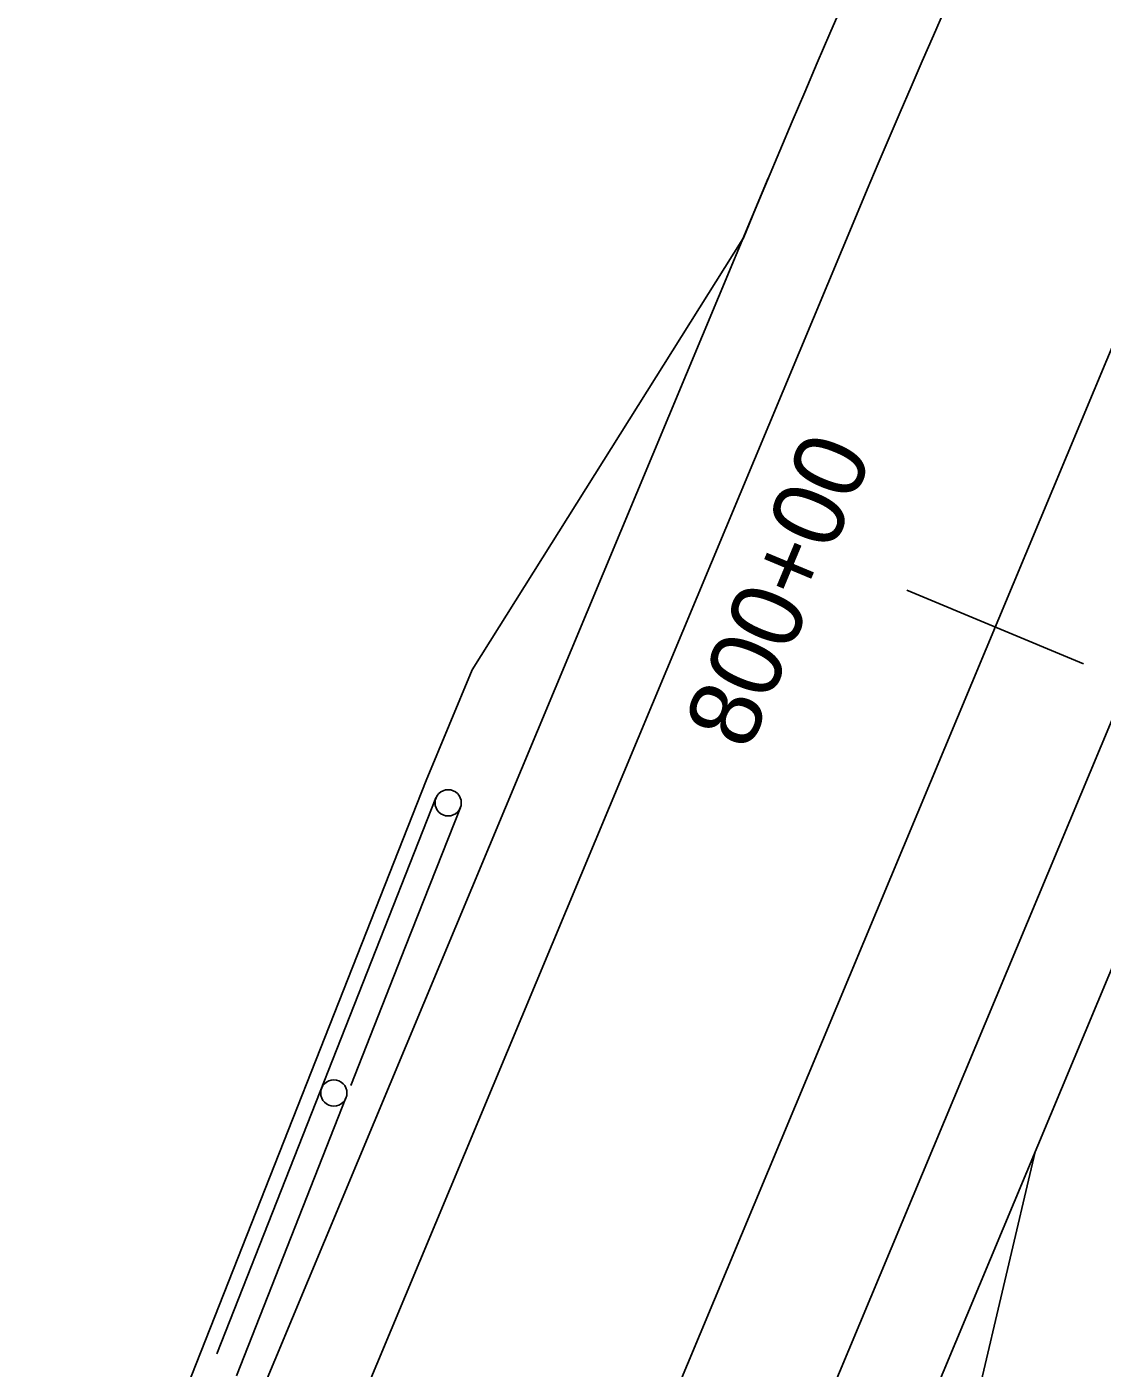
# Model space of a CAD drawing. Extents: x 1237212 to 1293764, y 379349 to 410301.
# Drawn here: x 1283439.3 to 1283529.3, y 404136.8 to 404249 of the extents above; entities that cross this region are included whole.
import ezdxf

# ---------------------------------------------------------------- set-up
doc = ezdxf.new("R2010")
doc.units = 0
for name, color, linetype in [('B-Tbl-Title Block', 7, 'Continuous'), ('B-Title Block (No Plot)', 7, 'Continuous'), ('R_Grid Annot', 7, 'Continuous'), ('R_Prop Surface', 7, 'Continuous'), ('R_Shld', 7, 'Continuous')]:
    doc.layers.add(name, color=color, linetype=linetype)

msp = doc.modelspace()

# ---------------------------------------------------------------- linework, layer by layer
at = {"layer": 'B-Tbl-Title Block'}
for p, q in [((1283334.68, 403816.57), (1283508.7, 404233.27)), ((1283367.9, 403802.7), (1283541.92, 404219.39))]:
    msp.add_line(p, q, dxfattribs=at)
msp.add_arc((1284344.24, 403884.33), 905.47, 138.45801, 157.33333, dxfattribs=at)
at = {"layer": 'B-Title Block (No Plot)'}
msp.add_line((1283356.82, 403807.32), (1283530.85, 404224.02), dxfattribs=at)
msp.add_line((1283356.82, 403807.32), (1283530.85, 404224.02), dxfattribs=at)
at = {"layer": 'R_Grid Annot'}
msp.add_lwpolyline([(1283512.93, 404201.89), (1283527.7, 404195.72)], dxfattribs=at)
msp.add_lwpolyline([(1283512.93, 404201.89), (1283527.7, 404195.72)], dxfattribs=at)
at = {"layer": 'R_Prop Surface'}
for points in [[(1283455.17, 404137.98), (1283473.51, 404184.5)], [(1283470.97, 404172.06), (1283475.56, 404183.69)], [(1283466.38, 404160.43), (1283470.97, 404172.06)], [(1283461.4, 404147.78), (1283465.98, 404159.41)], [(1283456.81, 404136.15), (1283461.4, 404147.78)]]:
    msp.add_lwpolyline(points, dxfattribs=at)
for centre in [(1283474.53, 404184.09), (1283464.96, 404159.81)]:
    msp.add_circle(centre, 1.1, dxfattribs=at)
at = {"layer": 'R_Shld'}
for p, q in [((1283327.3, 403819.65), (1283501.32, 404236.35)), ((1283476.55, 404195.22), (1283499.2, 404231.28)), ((1283448.45, 403974.81), (1283549.3, 404216.31)), ((1283472.69, 404185.96), (1283476.55, 404195.22)), ((1283408.48, 404023.13), (1283472.69, 404185.96)), ((1283513.92, 404113.43), (1283523.65, 404154.88))]:
    msp.add_line(p, q, dxfattribs=at)
msp.add_arc((1284344.24, 403884.33), 913.47, 136.3373, 157.67823, dxfattribs=at)

# ---------------------------------------------------------------- texts
at = {"layer": 'R_Grid Annot'}
msp.add_text('800+00', height=6, rotation=67.3333, dxfattribs=at).set_placement((1283499.68, 404188.3))

doc.saveas('drawing.dxf')
